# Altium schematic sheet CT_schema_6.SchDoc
size 430 x 429 mm
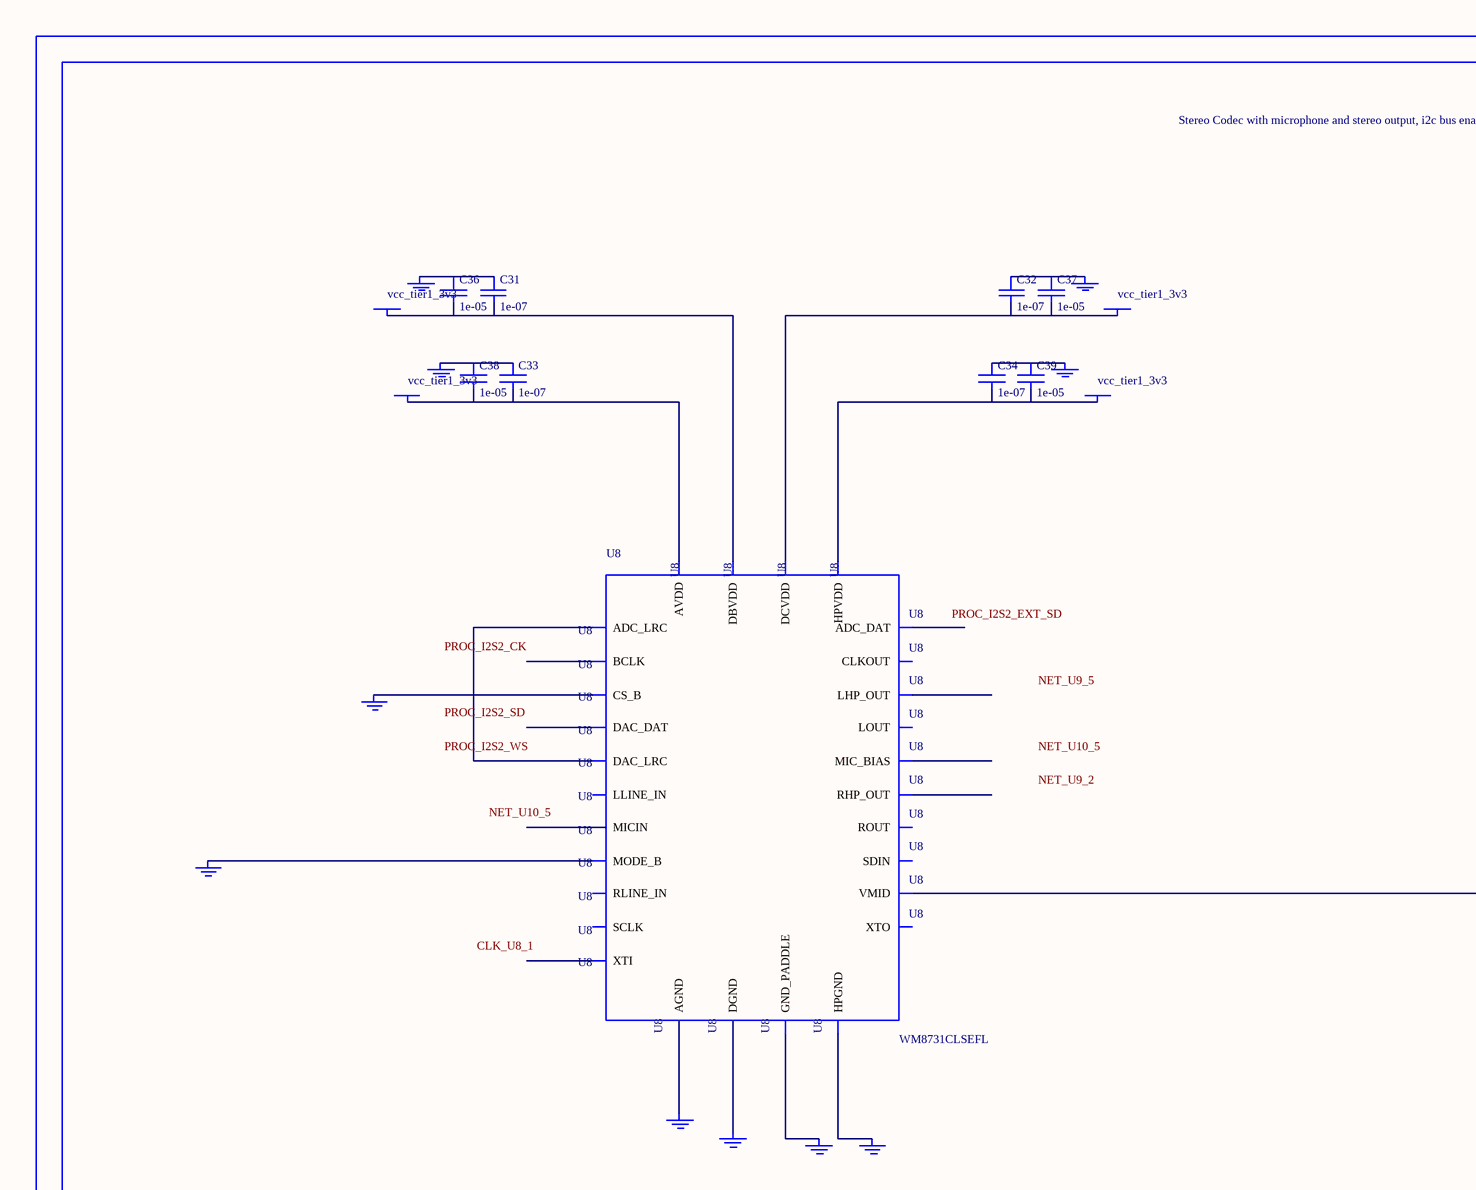
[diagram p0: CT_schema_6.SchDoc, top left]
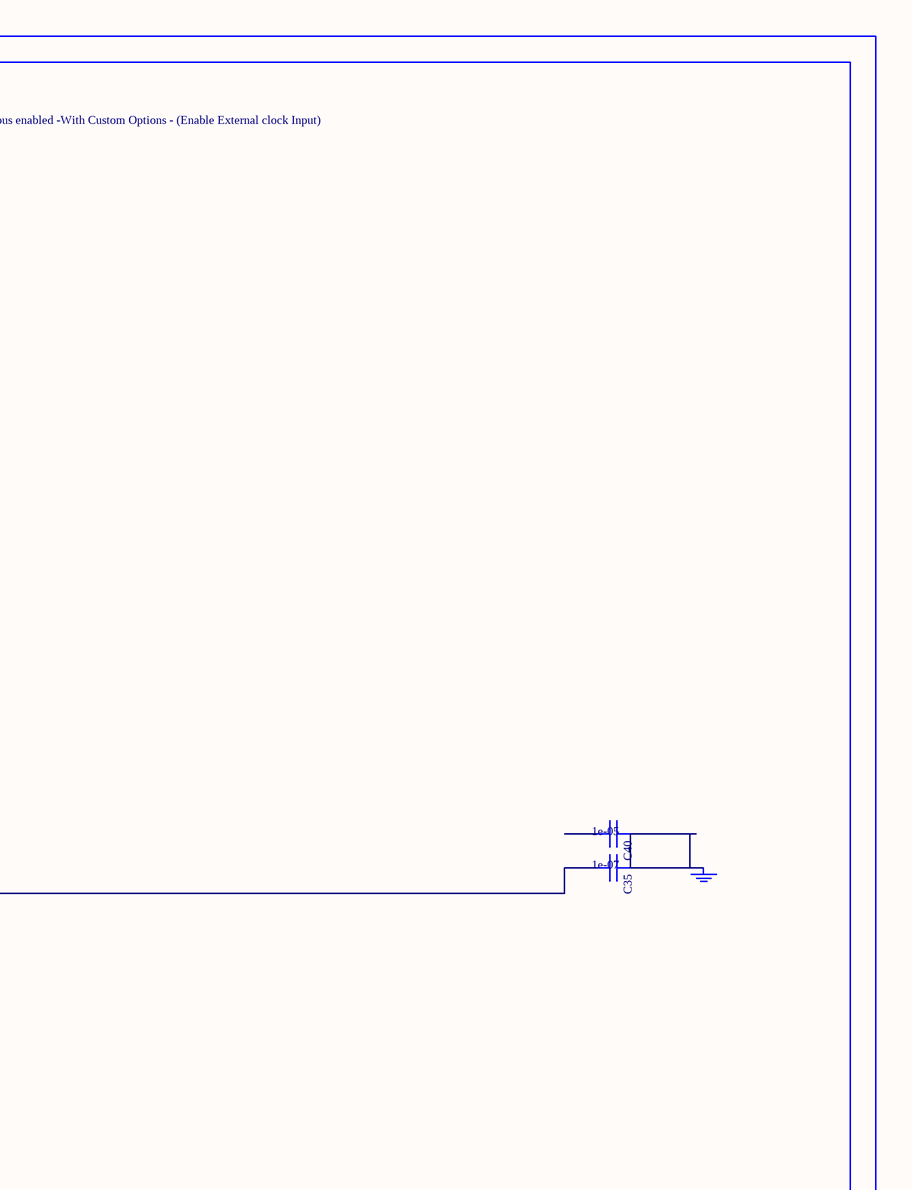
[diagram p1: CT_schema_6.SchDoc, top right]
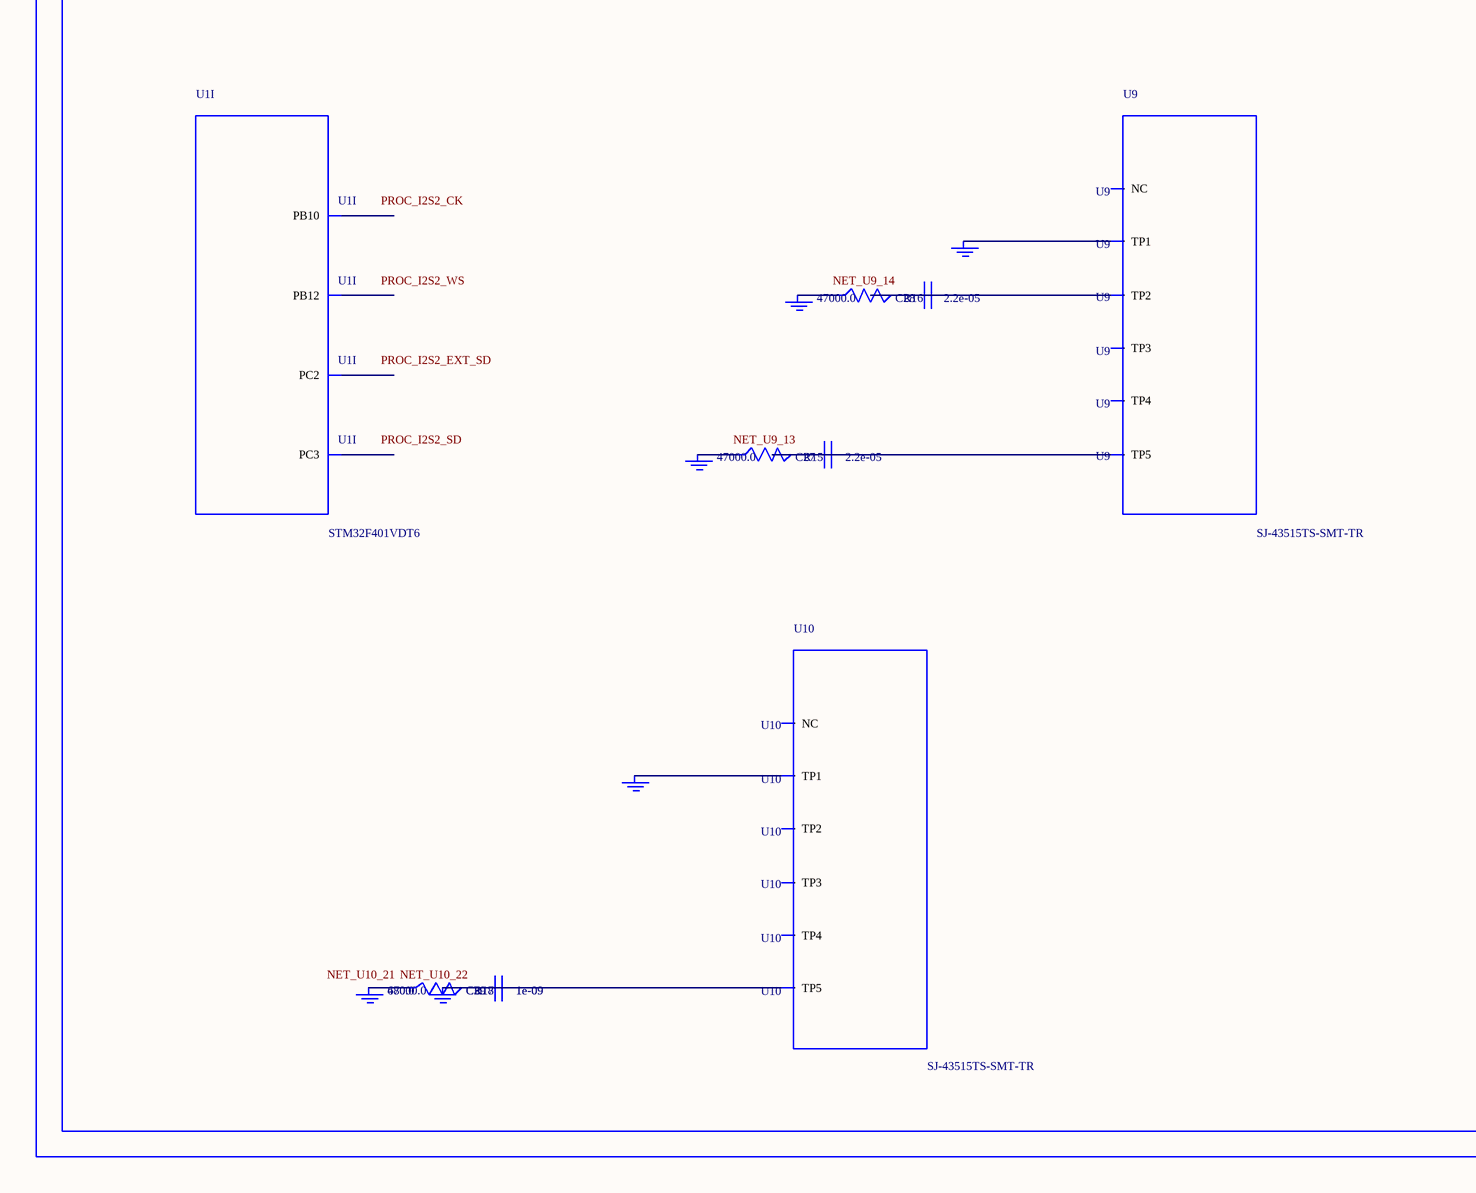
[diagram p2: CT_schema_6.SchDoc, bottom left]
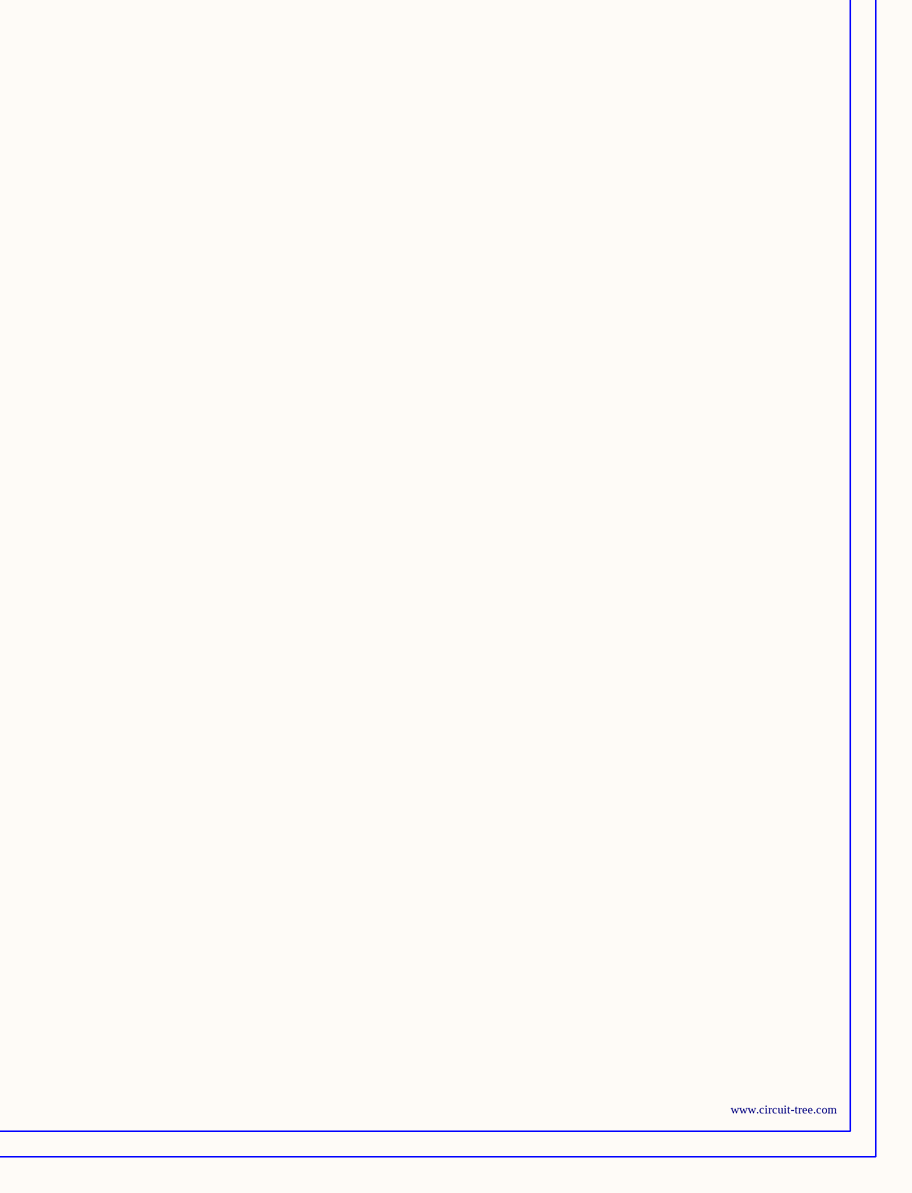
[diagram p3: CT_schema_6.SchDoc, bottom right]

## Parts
BORDER5  (no value)
C27  2.2e-05  [C1210]
C28  2.2e-05  [C1210]
C29  1e-09  [C0402]
C30  1e-09  [C0402]
C31  1e-07  [C0402]
C32  1e-07  [C0402]
C33  1e-07  [C0402]
C34  1e-07  [C0402]
C35  1e-07  [C0402]
C36  1e-05  [C0805]
C37  1e-05  [C0805]
C38  1e-05  [C0805]
C39  1e-05  [C0805]
C40  1e-05  [C0805]
GND_INSTANCE_5_0  (no value)
GND_INSTANCE_5_1  (no value)
GND_INSTANCE_5_2  (no value)
GND_INSTANCE_5_3  (no value)
GND_INSTANCE_5_4  (no value)
GND_INSTANCE_5_5  (no value)
GND_INSTANCE_5_6  (no value)
GND_INSTANCE_5_7  (no value)
GND_INSTANCE_5_8  (no value)
GND_INSTANCE_5_9  (no value)
GND_INSTANCE_5_10  (no value)
GND_INSTANCE_5_11  (no value)
GND_INSTANCE_5_12  (no value)
GND_INSTANCE_5_13  (no value)
GND_INSTANCE_5_14  (no value)
GND_INSTANCE_5_15  (no value)
GND_INSTANCE_5_16  (no value)
POWER_INSTANCE_5_0  vcc_tier1_3v3
POWER_INSTANCE_5_1  vcc_tier1_3v3
POWER_INSTANCE_5_2  vcc_tier1_3v3
POWER_INSTANCE_5_3  vcc_tier1_3v3
R15  47000.0  [R0603]
R16  47000.0  [R0603]
R17  47000.0  [R0603]
R18  680.0  [R0603]
U1  STM32F401VDT6  [LQFP100]  (part I of 10)
U8  WM8731CLSEFL  [QFN-28]
U9  SJ-43515TS-SMT-TR  [SJ-43515TS-SMT-TR]
U10  SJ-43515TS-SMT-TR  [SJ-43515TS-SMT-TR]

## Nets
NetC27_1: C27.1 C27.2 R15.2 U9.5(TP5)
NetC28_1: C28.1 C28.2 R16.2 U9.2(TP2)
NetC29_1: C29.1 C29.2 C30.1 C30.2 GND_INSTANCE_5_16.0(GND) R17.2 R18.2 U10.5(TP5)
NetC31_1: C31.1 C36.1 GND_INSTANCE_5_1.0(GND)
NetC31_2: C31.2 C36.2 POWER_INSTANCE_5_1.0(PWR) U8.5(DBVDD)
NetC32_1: C32.1 C37.1 GND_INSTANCE_5_0.0(GND)
NetC32_2: C32.2 C37.2 POWER_INSTANCE_5_0.0(PWR) U8.3(DCVDD)
NetC33_1: C33.1 C38.1 GND_INSTANCE_5_4.0(GND)
NetC33_2: C33.2 C38.2 POWER_INSTANCE_5_3.0(PWR) U8.18(AVDD)
NetC34_1: C34.1 C39.1 GND_INSTANCE_5_2.0(GND)
NetC34_2: C34.2 C39.2 POWER_INSTANCE_5_2.0(PWR) U8.12(HPVDD)
NetC35_1: C35.1 C40.1 GND_INSTANCE_5_5.0(GND)
NetC35_2: C35.2 U8.20(VMID)
NetGND_INSTANCE_5_3_0: GND_INSTANCE_5_3.0(GND) U8.15(HPGND)
NetGND_INSTANCE_5_6_0: GND_INSTANCE_5_6.0(GND) U8.25(MODE_B)
NetGND_INSTANCE_5_7_0: GND_INSTANCE_5_7.0(GND) U8.26(CS_B)
NetGND_INSTANCE_5_8_0: GND_INSTANCE_5_8.0(GND) U8.29(GND_PADDLE)
NetGND_INSTANCE_5_9_0: GND_INSTANCE_5_9.0(GND) U8.4(DGND)
NetGND_INSTANCE_5_10_0: GND_INSTANCE_5_10.0(GND) U8.19(AGND)
NetGND_INSTANCE_5_11_0: GND_INSTANCE_5_11.0(GND) U9.1(TP1)
NetGND_INSTANCE_5_12_0: GND_INSTANCE_5_12.0(GND) R16.1
NetGND_INSTANCE_5_13_0: GND_INSTANCE_5_13.0(GND) R15.1
NetGND_INSTANCE_5_14_0: GND_INSTANCE_5_14.0(GND) U10.1(TP1)
NetGND_INSTANCE_5_15_0: GND_INSTANCE_5_15.0(GND) R17.1 R18.1
NetU8_9: U8.9(DAC_LRC) U8.11(ADC_LRC)

Not connected (* = marked no-connect by the designer): C40 2; U1 17(PC2) 18(PC3) 47(PB10) 51(PB12); U8 1(XTI) 2(XTO) 6(CLKOUT) 7(BCLK) 8(DAC_DAT) 10(ADC_DAT) 13(LHP_OUT) 14(RHP_OUT) 16(LOUT) 17(ROUT) 21(MIC_BIAS) 22(MICIN) 23(RLINE_IN) 24(LLINE_IN) 27(SDIN) 28(SCLK); U9 3(TP3) 4(TP4) 6(NC); U10 2(TP2) 3(TP3) 4(TP4) 6(NC)

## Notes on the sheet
- Labels drawn without touching a wire or pin: CLK_U8_1, NET_U9_2, NET_U9_5, NET_U9_13, NET_U9_14, NET_U10_5, NET_U10_21, NET_U10_22, PROC_I2S2_CK, PROC_I2S2_EXT_SD, PROC_I2S2_SD, PROC_I2S2_WS

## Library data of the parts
BORDER5 = BORDER_PAGE5
C27 C28 = C1210C224K5RACTU
C29 C30 = C0402C102K3RAC
C31-C35 = C0402C104K3RACTU
C36-C40 = C0805C106K8RACTU
GND_INSTANCE_5_0-GND_INSTANCE_5_16 = GND
POWER_INSTANCE_5_0-POWER_INSTANCE_5_3 = PWR
R15-R17 = RC0603JR-0747KL
R18 = RC0603JR-07680RL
